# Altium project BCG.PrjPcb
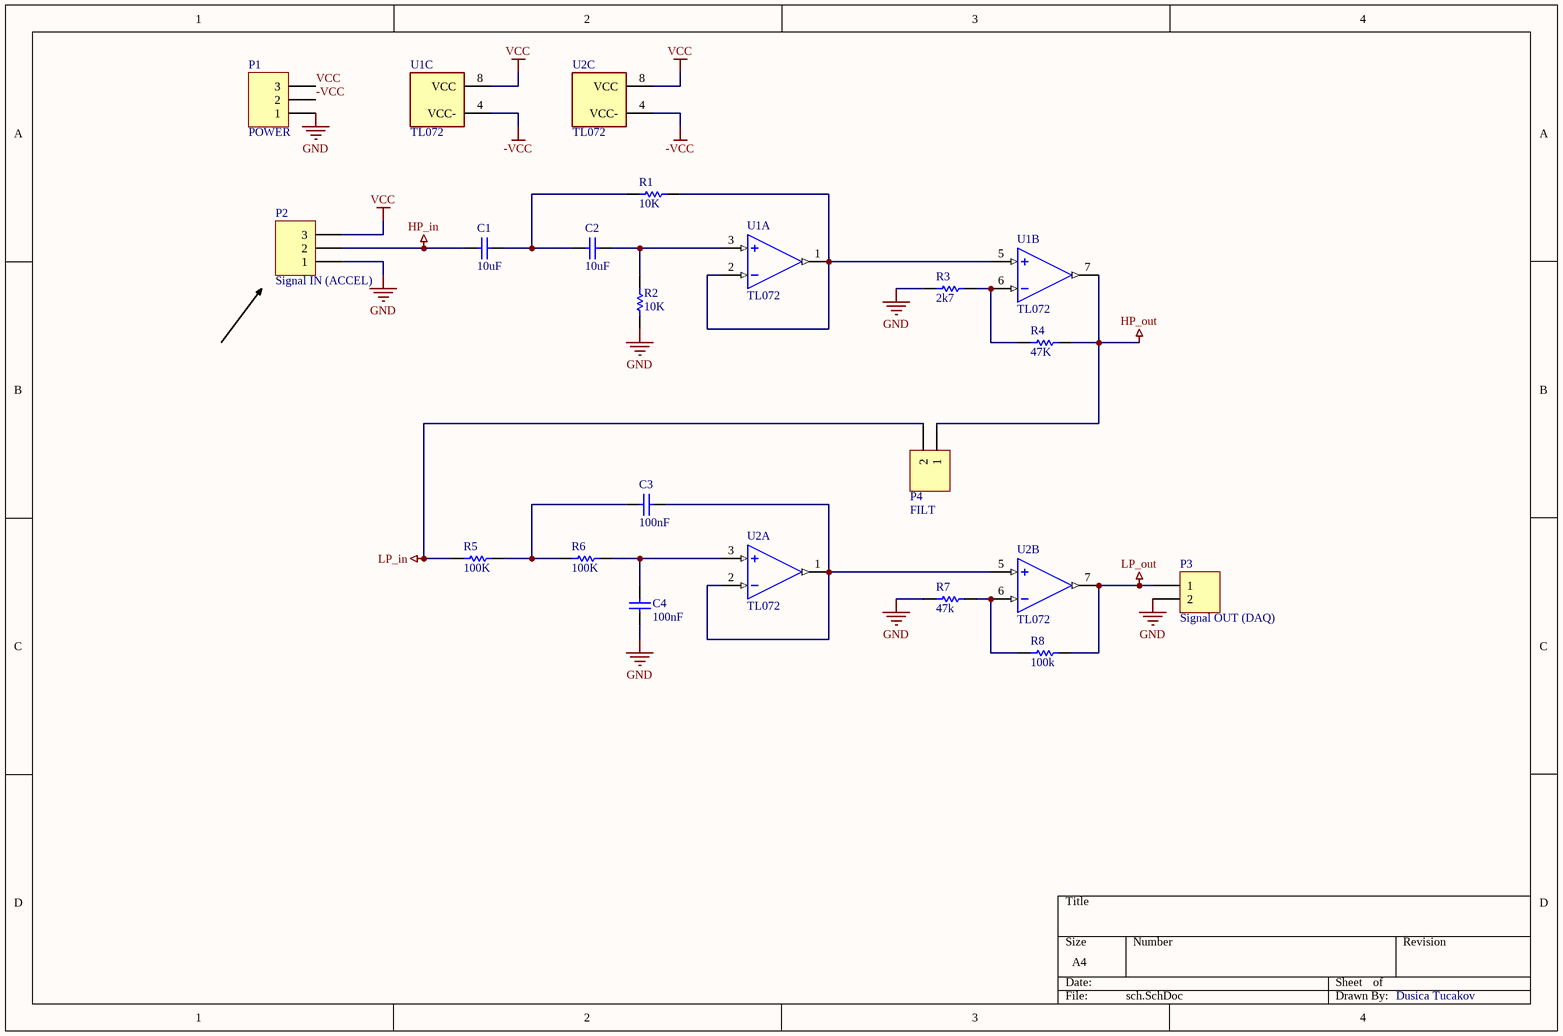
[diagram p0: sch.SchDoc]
1 sheet, 18 parts. Net scope: global (net labels, ports and power ports of the same name join across sheets).
Board file: pcb.PcbDoc

## Sheet sch.SchDoc
size A4; SheetNumber: 1; SheetTotal: 1

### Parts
C1  value 10uF  [CAP200]  (hidden comment: Cap)
C2  value 10uF  [CAP200]  (hidden comment: Cap)
C3  value 100nF  [CAP200]  (hidden comment: Cap)
C4  value 100nF  [CAP200]  (hidden comment: Cap)
P1  POWER  [DG301-5.0]
P2  Signal IN (ACCEL)  [HDR1X3]
P3  Signal OUT (DAQ)  [HDR1X2]
P4  FILT  [HDR1X2]
R1  value 10K  [AXIAL-0.4]  (hidden comment: Res1)
R2  value 10K  [AXIAL-0.4]  (hidden comment: Res1)
R3  value 2k7  [AXIAL-0.4]  (hidden comment: Res1)
R4  value 47K  [AXIAL-0.4]  (hidden comment: Res1)
R5  value 100K  [AXIAL-0.4]  (hidden comment: Res1)
R6  value 100K  [AXIAL-0.4]  (hidden comment: Res1)
R7  value 47k  [AXIAL-0.4]  (hidden comment: Res1)
R8  value 100k  [AXIAL-0.4]  (hidden comment: Res1)
U1  TL072  [DIP-8]  (parts A,B,C of 3)
U2  TL072  [DIP-8]  (parts A,B,C of 3)

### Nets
-VCC: P1.2 U1.4(VCC-) U2.4(VCC-)
GND: C4.1 P1.1 P2.1 P3.2 R2.2 R3.2 R7.2
HP_in: C1.2 P2.2
HP_out: P4.1 R4.1 U1.7(OUT2)
LP_in: P4.2 R5.2
LP_out: P3.1 R8.1 U2.7(OUT2)
VCC: P1.3 P2.3 U1.8(VCC) U2.8(VCC)
NetC1_1: C1.1 C2.2 R1.2
NetC2_1: C2.1 R2.1 U1.3(+IN1)
NetC3_1: C3.1 U2.1(OUT1) U2.2(-IN1) U2.5(+IN2)
NetC3_2: C3.2 R5.1 R6.1
NetC4_2: C4.2 R6.2 U2.3(+IN1)
NetR1_1: R1.1 U1.1(OUT1) U1.2(-IN1) U1.5(+IN2)
NetR3_1: R3.1 R4.2 U1.6(-IN2)
NetR7_1: R7.1 R8.2 U2.6(-IN2)

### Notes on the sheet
- Dusica Tucakov

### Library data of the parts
C1-C4 = Cap: Capacitor
P1 P2 = Header 3: Header, 3-Pin
P3 P4 = Header 2: Header, 2-Pin
R1-R8 = Res1: Resistor
U1 U2 = TL072: Dual standard operational amplifier 8-PDIP 0 to 70; MP: LM358P; MF: Texas Instruments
